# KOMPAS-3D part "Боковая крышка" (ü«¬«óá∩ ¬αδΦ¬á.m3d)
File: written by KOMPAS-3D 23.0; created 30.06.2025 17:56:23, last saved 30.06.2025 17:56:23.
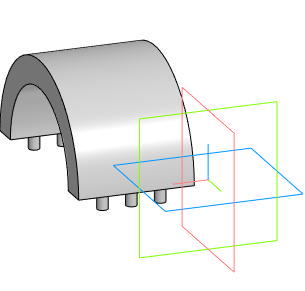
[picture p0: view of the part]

Document properties: Автор: Inspektor_Kot; Полное имя файла: I:\Autodesk Inventor Projects\2025 Варианты\Демовариант\Боковая крышка.m3d

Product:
- Part/product: Боковая крышка

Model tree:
1. Операция без истории:1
